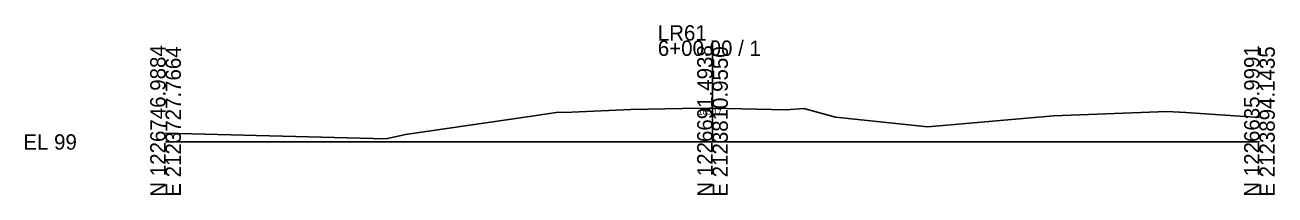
# Model space of a CAD drawing. Extents: x 2126751 to 2128979, y 1225108 to 1234639.
# Drawn here: x 2126750.9 to 2126979.4, y 1231107.5 to 1231138.6 of the extents above; entities that cross this region are included whole.
import ezdxf

# ---------------------------------------------------------------- set-up
doc = ezdxf.new("R2010")
doc.units = 0
for name, color, linetype in [('XS_CELL', 7, 'Continuous'), ('XS_X_GROUND', 7, 'Continuous'), ('XS_X_GROUND_TX', 7, 'Continuous')]:
    doc.layers.add(name, color=color, linetype=linetype)

msp = doc.modelspace()

# ---------------------------------------------------------------- linework, layer by layer
at = {"layer": 'XS_CELL'}
for p, q in [((2126876.61, 1231117.21), (2126876.61, 1231135.75)), ((2126776.61, 1231117.21), (2126876.61, 1231117.21)), ((2126876.61, 1231117.21), (2126976.61, 1231117.21))]:
    msp.add_line(p, q, dxfattribs=at)
at = {"layer": 'XS_X_GROUND'}
for p, q in [((2126820.49, 1231118.59), (2126843.17, 1231121.86)), ((2126843.17, 1231121.86), (2126848.02, 1231122.57)), ((2126848.02, 1231122.57), (2126850.87, 1231122.65)), ((2126850.87, 1231122.65), (2126861.66, 1231123.13)), ((2126861.66, 1231123.13), (2126871.07, 1231123.31)), ((2126871.07, 1231123.31), (2126876.04, 1231123.39)), ((2126876.04, 1231123.39), (2126876.61, 1231123.38)), ((2126876.61, 1231123.38), (2126879.28, 1231123.32)), ((2126879.28, 1231123.32), (2126890.07, 1231123.06)), ((2126890.07, 1231123.06), (2126893.31, 1231123.32)), ((2126893.31, 1231123.32), (2126899.08, 1231121.76)), ((2126899.08, 1231121.76), (2126915.98, 1231119.96)), ((2126915.98, 1231119.96), (2126938.93, 1231121.97)), ((2126938.93, 1231121.97), (2126959.68, 1231122.75)), ((2126959.68, 1231122.75), (2126963.17, 1231122.57)), ((2126963.17, 1231122.57), (2126976.61, 1231121.68)), ((2126776.61, 1231118.82), (2126783.82, 1231118.62)), ((2126783.82, 1231118.62), (2126816.97, 1231117.76)), ((2126816.97, 1231117.76), (2126820.49, 1231118.59))]:
    msp.add_line(p, q, dxfattribs=at)

# ---------------------------------------------------------------- texts
at = {"layer": 'XS_CELL'}
for s, p in [('LR61', (2126866.61, 1231135.75)), ('6+00.00 / 1', (2126866.61, 1231132.95)), ('EL 99', (2126750.61, 1231115.81))]:
    msp.add_text(s, height=2.8, dxfattribs=at).set_placement(p)
for s, p in [('N 1226746.9884', (2126776.61, 1231107.21)), ('E 2123727.7664', (2126779.41, 1231107.21)), ('N 1226691.4938', (2126876.61, 1231107.21)), ('E 2123810.9550', (2126879.41, 1231107.21)), ('N 1226635.9991', (2126976.61, 1231107.21)), ('E 2123894.1435', (2126979.41, 1231107.21))]:
    msp.add_text(s, height=2.8, rotation=90, dxfattribs=at).set_placement(p)
at = {"layer": 'XS_X_GROUND_TX'}
msp.add_text('105.17', height=1, dxfattribs=at).set_placement((2126874.05, 1231122.22))

doc.saveas('drawing.dxf')
